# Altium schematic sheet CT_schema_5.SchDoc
size 279 x 236 mm
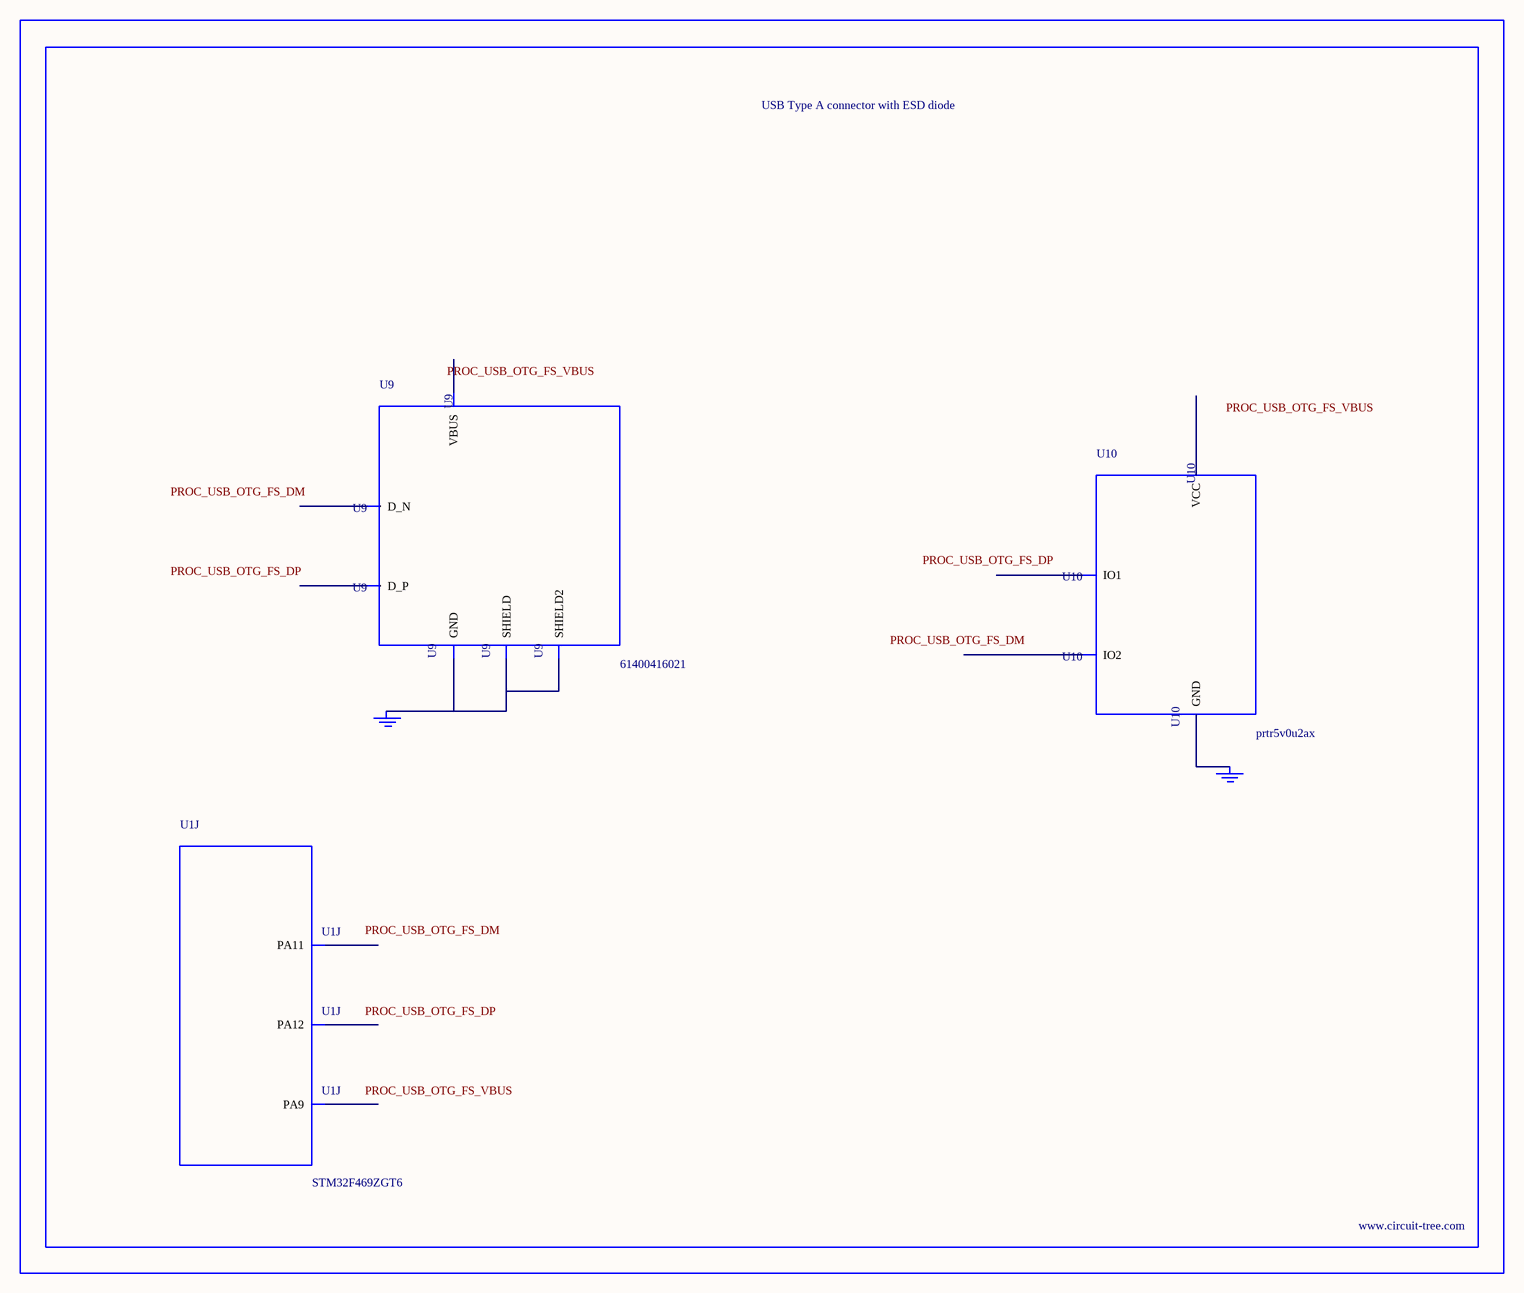
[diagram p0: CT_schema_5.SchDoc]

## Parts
BORDER4  (no value)
GND_INSTANCE_4_0  (no value)
GND_INSTANCE_4_1  (no value)
U1  STM32F469ZGT6  [LQFP144]  (part J of 12)
U9  61400416021  [USB-A-H]
U10  prtr5v0u2ax  [SOT143B]

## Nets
NetGND_INSTANCE_4_0_0: GND_INSTANCE_4_0.0(GND) U9.4(GND) U9.5(SHIELD) U9.6(SHIELD2)
NetGND_INSTANCE_4_1_0: GND_INSTANCE_4_1.0(GND) U10.1(GND)

Not connected (* = marked no-connect by the designer): U1 103(PA9) 105(PA11) 106(PA12); U9 1(VBUS) 2(D_N) 3(D_P); U10 2(IO1) 3(IO2) 4(VCC)

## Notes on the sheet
- Labels drawn without touching a wire or pin: PROC_USB_OTG_FS_DM, PROC_USB_OTG_FS_DP, PROC_USB_OTG_FS_VBUS

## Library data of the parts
BORDER4 = BORDER_PAGE4
GND_INSTANCE_4_0 GND_INSTANCE_4_1 = GND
